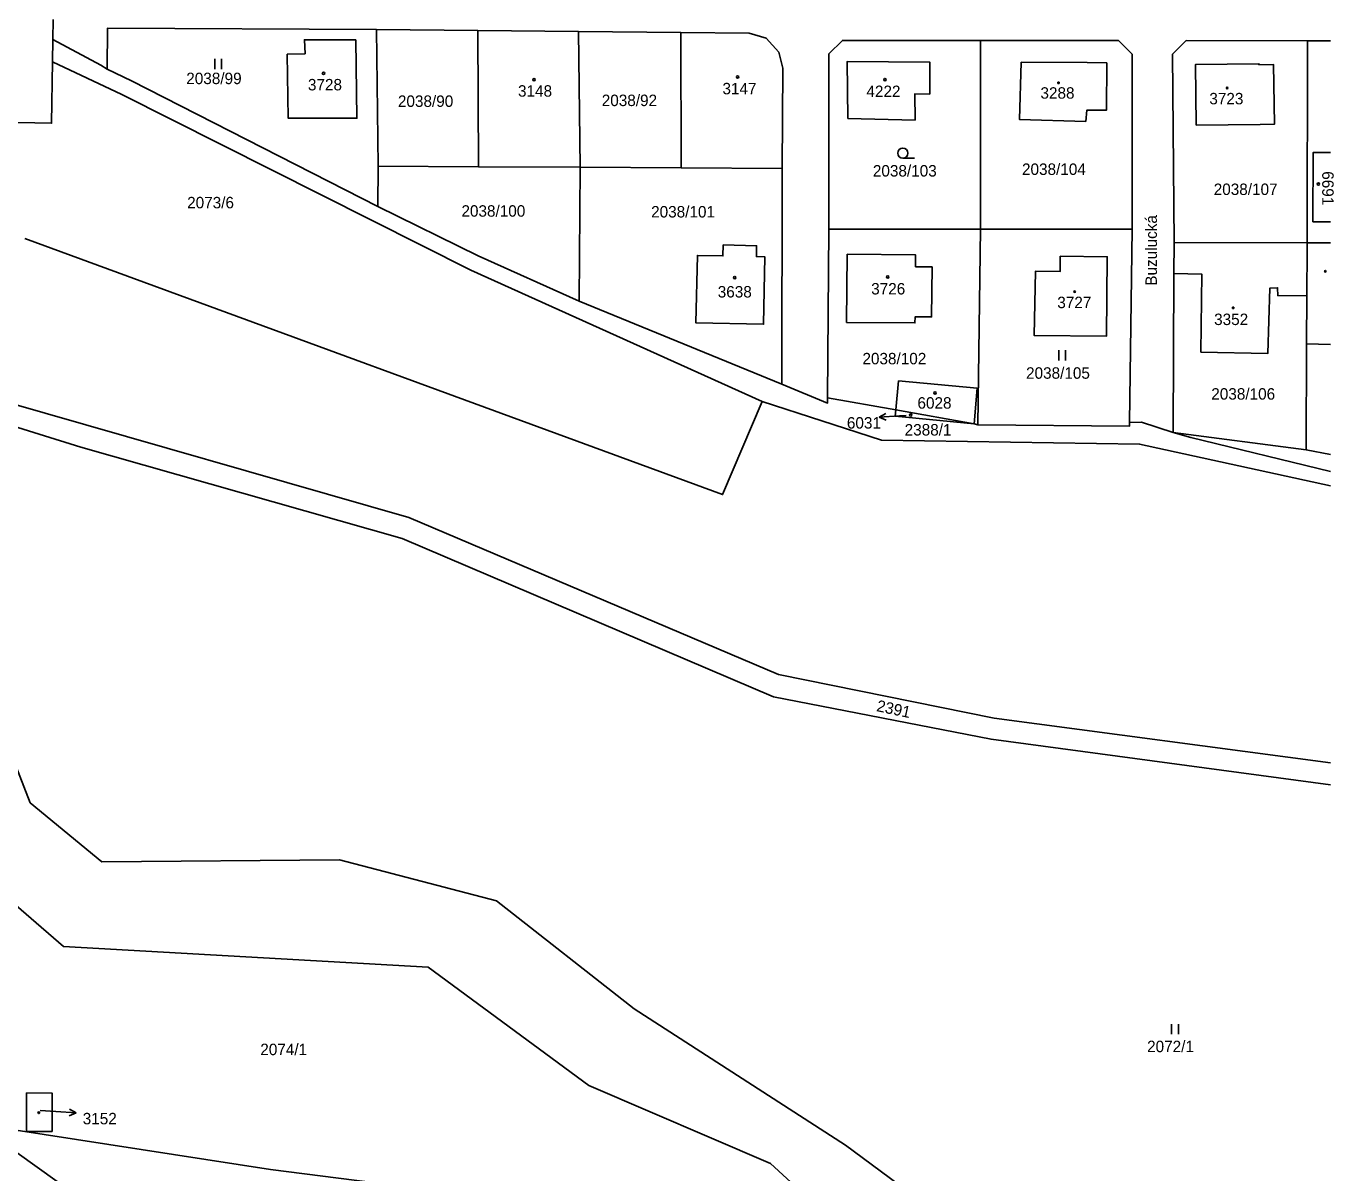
# Model space of a CAD drawing. Extents: x -667048 to -665920, y -1108425 to -1107247.
# Drawn here: x -666121 to -665926.8, y -1108187.1 to -1108016.8 of the extents above; entities that cross this region are included whole.
import ezdxf

# ---------------------------------------------------------------- set-up
doc = ezdxf.new("R2010")
doc.units = 0
for name, color, linetype in [('Default', 7, 'Continuous'), ('Hranice parcel', 7, 'Continuous'), ('Parcelní čísla', 7, 'Continuous'), ('Pop_ PČ_ popisy', 7, 'Continuous'), ('Značky budov', 7, 'Continuous'), ('Značky kultur', 7, 'Continuous')]:
    doc.layers.add(name, color=color, linetype=linetype)

# ---------------------------------------------------------------- blocks, each defined once
blk = doc.blocks.new('3.041')
at = {"layer": 'Default'}
blk.add_line((8, 0), (1758, 0), dxfattribs=at)
blk.add_circle((8, 750), 750, dxfattribs=at)
blk = doc.blocks.new('4.021')
at = {"layer": 'Default'}
blk.add_circle((-7, 1), 175, dxfattribs=at)
blk = doc.blocks.new('10291')
at = {"layer": 'Default'}
for p, q in [((0, 3001), (-500, 2001)), ((0, 1), (0, 3001)), ((0, 3001), (500, 2001))]:
    blk.add_line(p, q, dxfattribs=at)
blk = doc.blocks.new('3.061')
at = {"layer": 'Default'}
for p, q in [((-511, -1), (-511, 1499)), ((489, -1), (489, 1499))]:
    blk.add_line(p, q, dxfattribs=at)

msp = doc.modelspace()

# ---------------------------------------------------------------- linework, layer by layer
at = {"layer": 'Hranice parcel'}
for points in [[(-666116.97, -1108015.85), (-666117.01, -1108018.78)], [(-666108.91, -1108023.2), (-666108.88, -1108017.1), (-666068.93, -1108017.34)], [(-666068.93, -1108017.34), (-666068.71, -1108037.6)], [(-666068.93, -1108017.34), (-666053.93, -1108017.48)], [(-666053.82, -1108037.69), (-666053.93, -1108017.48)], [(-666053.93, -1108017.48), (-666038.97, -1108017.62)], [(-666038.97, -1108017.62), (-666023.78, -1108017.76)], [(-666038.97, -1108017.62), (-666038.71, -1108037.78)], [(-666117.01, -1108018.78), (-666117.06, -1108022.14)], [(-666117.01, -1108018.78), (-666109.87, -1108022.61)], [(-666072.01, -1108018.83), (-666071.85, -1108030.49), (-666082.05, -1108030.49), (-666082.21, -1108021), (-666079.56, -1108020.92), (-666079.64, -1108018.83), (-666072.01, -1108018.83)], [(-666023.78, -1108017.76), (-666013.63, -1108017.85), (-666011.08, -1108018.6), (-666009.24, -1108020.69), (-666008.62, -1108023.07), (-666008.71, -1108037.96)], [(-666023.7, -1108037.87), (-666023.78, -1108017.76)], [(-666001.81, -1108046.94), (-666001.79, -1108020.93), (-665999.79, -1108018.93), (-665979.28, -1108018.95)], [(-665979.3, -1108046.96), (-665979.28, -1108018.95)], [(-665979.28, -1108018.95), (-665958.77, -1108018.96), (-665956.77, -1108020.96), (-665956.79, -1108046.98)], [(-665950.77, -1108020.97), (-665948.76, -1108018.97), (-665930.75, -1108018.98)], [(-665930.75, -1108018.98), (-665930.77, -1108048.99)], [(-665930.75, -1108018.98), (-665927.32, -1108018.98)], [(-665950.55, -1108048.93), (-665950.77, -1108020.97)], [(-666117.06, -1108022.14), (-666117.18, -1108031.25), (-666142.12, -1108030.72)], [(-666106.76, -1108026.99), (-666117.06, -1108022.14)], [(-666109.87, -1108022.61), (-666108.91, -1108023.2)], [(-666108.91, -1108023.2), (-666105.33, -1108024.92), (-666068.75, -1108043.59)], [(-665988.97, -1108030.78), (-665989.04, -1108026.89), (-665986.82, -1108026.9), (-665986.79, -1108022.17), (-665999.08, -1108022.09), (-665998.97, -1108030.53), (-665988.97, -1108030.78)], [(-665973.24, -1108022.17), (-665973.47, -1108030.7), (-665963.65, -1108030.96), (-665963.48, -1108029.28), (-665960.6, -1108029.3), (-665960.55, -1108022.26)], [(-665960.55, -1108022.26), (-665963.44, -1108022.24), (-665973.24, -1108022.17)], [(-665947.26, -1108031.53), (-665937.76, -1108031.42), (-665935.65, -1108031.39), (-665935.76, -1108022.53), (-665937.96, -1108022.56), (-665937.96, -1108022.41), (-665947.37, -1108022.52), (-665947.26, -1108031.53)], [(-666011.71, -1108072.54), (-666054.94, -1108053.05), (-666106.76, -1108026.99)], [(-665927.32, -1108045.87), (-665929.92, -1108045.86), (-665929.88, -1108035.57), (-665927.32, -1108035.56)], [(-666068.75, -1108043.59), (-666068.71, -1108037.6)], [(-666068.71, -1108037.6), (-666053.82, -1108037.69)], [(-666038.71, -1108037.78), (-666053.82, -1108037.69)], [(-666038.84, -1108057.65), (-666038.71, -1108037.78)], [(-666038.71, -1108037.78), (-666023.7, -1108037.87)], [(-666008.71, -1108037.96), (-666023.7, -1108037.87)], [(-666008.71, -1108037.96), (-666008.75, -1108069.96)], [(-666038.84, -1108057.65), (-666053.88, -1108050.91), (-666068.75, -1108043.59)], [(-666186.54, -1108047.13), (-666125.26, -1108075.48), (-666112.86, -1108079.33), (-666065.13, -1108092.87), (-666009.99, -1108116.41), (-665977.71, -1108122.7), (-665927.32, -1108129.44)], [(-666011.71, -1108072.54), (-666017.56, -1108086.38), (-666121.17, -1108048.37)], [(-666002.01, -1108071.98), (-666001.81, -1108046.94)], [(-665979.3, -1108046.96), (-666001.81, -1108046.94)], [(-665979.69, -1108076.01), (-665979.3, -1108046.96)], [(-665979.3, -1108046.96), (-665956.79, -1108046.98)], [(-665956.79, -1108046.98), (-665957.14, -1108075.66)], [(-666017.49, -1108049.31), (-666017.52, -1108050.94), (-666021.3, -1108050.87), (-666021.54, -1108060.89), (-666011.49, -1108061.08), (-666011.3, -1108051.06), (-666012.55, -1108051.04), (-666012.52, -1108049.43), (-666017.49, -1108049.31)], [(-665999.17, -1108060.83), (-665989.01, -1108060.88), (-665989, -1108059.98), (-665986.54, -1108060), (-665986.47, -1108052.56), (-665988.93, -1108052.54), (-665988.91, -1108050.78), (-665999.07, -1108050.68), (-665999.17, -1108060.83)], [(-665950.57, -1108053.56), (-665950.55, -1108048.93)], [(-665930.77, -1108048.99), (-665950.55, -1108048.93)], [(-665930.82, -1108056.79), (-665930.78, -1108049.89), (-665930.77, -1108048.99)], [(-665930.77, -1108048.99), (-665927.32, -1108048.99)], [(-665967.45, -1108050.99), (-665967.47, -1108053.25), (-665971.14, -1108053.22), (-665971.29, -1108062.77), (-665960.58, -1108062.87), (-665960.46, -1108051.06), (-665967.45, -1108050.99)], [(-665950.67, -1108077.14), (-665950.57, -1108053.56)], [(-665930.82, -1108056.79), (-665935.14, -1108056.85), (-665935.18, -1108055.65), (-665936.31, -1108055.71), (-665936.6, -1108065.41), (-665946.56, -1108065.2), (-665946.44, -1108053.63), (-665950.57, -1108053.56)], [(-666008.75, -1108069.96), (-666038.84, -1108057.65)], [(-665930.86, -1108063.97), (-665930.82, -1108056.79)], [(-665930.95, -1108079.72), (-665930.86, -1108063.97)], [(-665930.86, -1108063.97), (-665927.32, -1108064.1)], [(-666008.75, -1108069.96), (-666001.98, -1108072.79), (-666002.01, -1108071.98)], [(-665991.84, -1108073.78), (-665991.43, -1108069.5), (-665979.78, -1108070.56), (-665980.24, -1108075.84)], [(-665991.84, -1108073.78), (-666002.01, -1108071.98)], [(-666124.17, -1108072.57), (-666064.15, -1108089.77), (-666009.29, -1108113.1), (-665977.25, -1108119.58), (-665927.32, -1108126.18)], [(-665927.32, -1108085.07), (-665955.66, -1108078.88), (-665993.98, -1108078.27), (-666011.71, -1108072.54)], [(-665980.24, -1108075.84), (-665991.93, -1108074.72), (-665991.84, -1108073.78)], [(-665991.84, -1108073.78), (-665980.24, -1108075.84)], [(-665979.69, -1108076.01), (-665980.24, -1108075.84)], [(-665957.14, -1108075.66), (-665957.15, -1108076.21), (-665979.69, -1108076.01)], [(-665957.14, -1108075.66), (-665955.38, -1108075.62)], [(-665955.38, -1108075.62), (-665950.67, -1108077.14)], [(-665948.08, -1108077.91), (-665950.67, -1108077.14)], [(-665950.67, -1108077.14), (-665930.95, -1108079.72)], [(-665927.32, -1108082.96), (-665948.08, -1108077.91)], [(-665930.95, -1108079.72), (-665927.32, -1108080.43)], [(-666157.01, -1108119.68), (-666151.55, -1108116.25), (-666134.26, -1108115.7), (-666124.35, -1108121.77), (-666120.37, -1108132.13), (-666109.74, -1108140.9), (-666074.44, -1108140.6), (-666051.14, -1108146.66), (-666030.68, -1108162.7), (-665999.31, -1108182.94), (-665978.14, -1108198.63), (-665960.5, -1108216.92), (-665949.27, -1108234.66), (-665927.32, -1108251.64)], [(-665957.88, -1108245.03), (-665984.95, -1108209.07), (-666010.44, -1108185.66), (-666037.45, -1108174.12), (-666061.27, -1108156.51), (-666115.42, -1108153.44), (-666143.9, -1108128.81), (-666152.14, -1108131.37)], [(-666117.1, -1108180.95), (-666117.08, -1108175.24), (-666120.9, -1108175.2), (-666120.92, -1108180.91), (-666117.1, -1108180.95)], [(-666127.94, -1108179.89), (-666084.69, -1108186.57), (-666061.76, -1108189.5), (-666037.52, -1108196.85), (-665981.57, -1108223.66), (-665957.88, -1108245.03)], [(-665927.32, -1108275.69), (-665963.06, -1108243.86), (-666040.05, -1108204.21), (-666063.13, -1108194.59), (-666078.83, -1108193.85), (-666081.36, -1108193.73), (-666110.76, -1108192.34), (-666127.93, -1108180.1)]]:
    msp.add_lwpolyline(points, dxfattribs=at)
at = {"layer": 'Pop_ PČ_ popisy'}
for points in [[(-665990.34, -1108074.64), (-665991.31, -1108074.7)], [(-666118.87, -1108177.79), (-666116.55, -1108177.95)]]:
    msp.add_lwpolyline(points, dxfattribs=at)

# ---------------------------------------------------------------- block references
for p, xscale, yscale, rotation in [((-665991.31, -1108074.7), 0.001, 0.0010000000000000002, 92.99999999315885), ((-666116.55, -1108177.95), 0.0010000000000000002, 0.001, -94.00000004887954)]:
    msp.add_blockref('10291', p, dxfattribs=dict(at, xscale=xscale, yscale=yscale, rotation=rotation))
at = {"layer": 'Značky budov'}
for p, xscale, yscale in [((-666076.81, -1108023.82), 0.0010000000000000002, 0.0010000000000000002), ((-666045.55, -1108024.77), 0.0010000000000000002, 0.0010000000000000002), ((-666015.34, -1108024.35), 0.0010000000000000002, 0.0010000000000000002), ((-665993.46, -1108024.76), 0.0010000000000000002, 0.0010000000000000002), ((-665967.7, -1108025.24), 0.0006700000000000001, 0.0006700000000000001), ((-665942.66, -1108026), 0.0006700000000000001, 0.0006700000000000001), ((-665929.1, -1108040.28), 0.0010000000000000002, 0.0010000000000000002), ((-666015.76, -1108054.16), 0.0010000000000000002, 0.0010000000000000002), ((-665993.04, -1108054.05), 0.0010000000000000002, 0.0010000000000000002), ((-665928.08, -1108053.21), 0.0006700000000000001, 0.0006700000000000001), ((-665965.29, -1108056.24), 0.0006700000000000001, 0.0006700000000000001), ((-665941.77, -1108058.64), 0.0006700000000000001, 0.0006700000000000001), ((-665986.01, -1108071.27), 0.0010000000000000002, 0.0010000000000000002), ((-665989.62, -1108074.56), 0.0010000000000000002, 0.0010000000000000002), ((-666119.08, -1108178.14), 0.0006700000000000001, 0.0006700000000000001)]:
    msp.add_blockref('4.021', p, dxfattribs=dict(at, xscale=xscale, yscale=yscale))
at = {"layer": 'Značky kultur', "xscale": 0.0010000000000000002, "yscale": 0.0010000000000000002}
for name, p in [('3.061', (-666092.44, -1108023.19)), ('3.041', (-665990.82, -1108036.42)), ('3.061', (-665967.15, -1108066.44)), ('3.061', (-665950.4, -1108166.48))]:
    msp.add_blockref(name, p, dxfattribs=at)

# ---------------------------------------------------------------- texts
at = {"layer": 'Parcelní čísla'}
for s, p in [('2038/99', (-666097.19, -1108025.43)), ('3728', (-666079.13, -1108026.36)), ('3147', (-666017.59, -1108026.94)), ('2038/90', (-666065.77, -1108028.81)), ('3148', (-666047.94, -1108027.29)), ('2038/92', (-666035.51, -1108028.69)), ('4222', (-665996.22, -1108027.35)), ('3288', (-665970.38, -1108027.59)), ('3723', (-665945.31, -1108028.43)), ('2038/104', (-665973.12, -1108038.91)), ('2038/103', (-665995.26, -1108039.15)), ('2038/107', (-665944.66, -1108041.89)), ('2073/6', (-666097.06, -1108043.87)), ('2038/100', (-666056.34, -1108045.11)), ('2038/101', (-666028.18, -1108045.23)), ('3638', (-666018.29, -1108057.11)), ('3726', (-665995.51, -1108056.66)), ('3727', (-665967.88, -1108058.69)), ('3352', (-665944.6, -1108061.2)), ('2038/102', (-665996.81, -1108067.03)), ('2038/105', (-665972.52, -1108069.17)), ('6028', (-665988.64, -1108073.61)), ('2038/106', (-665945.02, -1108072.27)), ('6031', (-665999.12, -1108076.57)), ('2388/1', (-665990.54, -1108077.6)), ('2074/1', (-666086.2, -1108169.59)), ('2072/1', (-665954.55, -1108169.15)), ('3152', (-666112.56, -1108179.86))]:
    msp.add_text(s, height=1.7, dxfattribs=at).set_placement(p)
for s, rotation, p in [('6691', 270, (-665928.55, -1108038.36)), ('2391', 348, (-665994.81, -1108118.5))]:
    msp.add_text(s, height=1.7, rotation=rotation, dxfattribs=at).set_placement(p)
at = {"layer": 'Pop_ PČ_ popisy'}
msp.add_text('Buzulucká', height=1.7, rotation=90, dxfattribs=at).set_placement((-665953.09, -1108055.36))

doc.saveas('drawing.dxf')
